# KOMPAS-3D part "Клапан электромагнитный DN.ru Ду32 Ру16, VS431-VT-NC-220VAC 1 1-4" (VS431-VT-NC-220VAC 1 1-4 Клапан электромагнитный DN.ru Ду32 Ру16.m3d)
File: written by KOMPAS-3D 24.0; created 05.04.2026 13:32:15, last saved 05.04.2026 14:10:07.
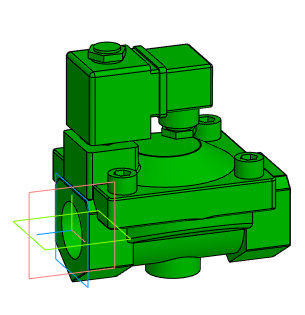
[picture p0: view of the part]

Document properties: Автор: artio; Полное имя файла: C:\Users\artio\OneDrive\Рабочий стол\Клапан электромагнитный DN.ru\VS431\VS431-VT-NC\VS431-VT-NC-220VAC\Ду32\VS431-VT-NC-220VAC 1 1-4 Клапан электромагнитный DN.ru Ду32 Ру16.m3d

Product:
- Body: Тело 1  | qty 1
    Масса: 3.709873
- Part/product: Клапан электромагнитный DN.ru Ду32 Ру16  | designation VS431-VT-NC-220VAC 1 1-4
    Масса: 1.701
    Раздел спецификации: Прочие изделия
    Примечание: D130-04715
    additional columns: ef56311e-7521-43dc-8291-0e6108b3d81d; artio; c; Шероховатость не задана; Да

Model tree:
1. Операция без истории:1

Expressions: VS431-VT-NC-220VAC 1 1-4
